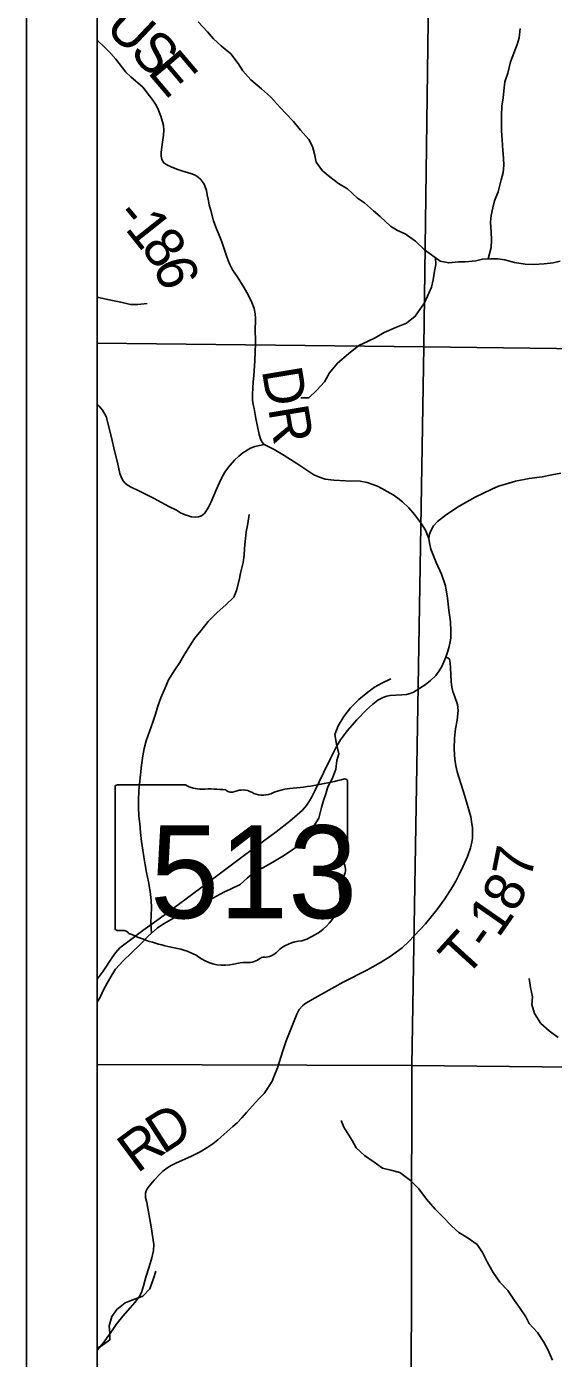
# Model space of a CAD drawing. Extents: x 0 to 34, y 0 to 22.
# Drawn here: x 23.417 to 24.164, y 15.161 to 17.051 of the extents above; entities that cross this region are included whole.
import ezdxf

# ---------------------------------------------------------------- set-up
doc = ezdxf.new("R2010")
doc.units = 0
for name, color, linetype in [('GM_X_Corporation', 7, 'Continuous'), ('GM_X_Minor_River', 7, 'Continuous'), ('GM_X_State_Route', 7, 'Continuous'), ('GM_X_State_Shield', 7, 'Continuous'), ('GM_X_Township_Road', 7, 'Continuous'), ('GM_X_Township_Road_Text', 7, 'Continuous'), ('SH_Data', 7, 'Continuous')]:
    doc.layers.add(name, color=color, linetype=linetype)

msp = doc.modelspace()

# ---------------------------------------------------------------- linework, layer by layer
at = {"layer": 'GM_X_Corporation'}
msp.add_lwpolyline([(23.5167, 20.3276), (23.5167, 14.5642), (23.7464, 14.562), (24.4108, 14.5557), (24.414, 14.5556), (24.9788, 14.5503), (25.0494, 14.5496), (25.56, 14.5392), (26.009, 14.53), (26.3333, 14.5233), (26.7998, 14.5186), (27.0057, 14.5136), (27.0124, 14.988), (27.0234, 16.6611), (27.0349, 17.5522)], dxfattribs=at)
msp.add_lwpolyline([(23.5167, 20.3276), (23.5167, 14.5642), (23.7464, 14.562), (24.4108, 14.5557), (24.414, 14.5556), (24.9788, 14.5503), (25.0494, 14.5496), (25.56, 14.5392), (26.009, 14.53), (26.3333, 14.5233), (26.7998, 14.5186), (27.0057, 14.5136), (27.0124, 14.988), (27.0234, 16.6611), (27.0349, 17.5522)], dxfattribs=at)
for points in [[(23.5167, 17.6305), (23.5167, 16.6012), (23.9803, 16.5962), (23.994, 17.626)], [(25.0136, 17.617), (24.9957, 16.5834), (23.9803, 16.5962), (23.994, 17.626)], [(23.5167, 16.6012), (23.5167, 15.5777), (23.9634, 15.5762), (23.9803, 16.5962)], [(23.9803, 16.5962), (24.9957, 16.5834), (24.9795, 15.5656), (23.9634, 15.5762)], [(23.5167, 15.5777), (23.5167, 14.5671), (23.9615, 14.5614), (23.9614, 14.5662), (23.9634, 15.5762)], [(23.9634, 15.5762), (24.9795, 15.5656), (24.9754, 14.552), (23.9615, 14.5614), (23.9614, 14.5662)]]:
    msp.add_lwpolyline(points, close=True, dxfattribs=at)
at = {"layer": 'GM_X_Minor_River'}
for points in [[(23.6601, 17.0576), (23.6734, 17.0433), (23.6818, 17.0334), (23.6928, 17.0232), (23.7065, 17.0119), (23.7168, 16.9982), (23.7236, 16.988), (23.7347, 16.9751), (23.7499, 16.9623), (23.7628, 16.9509), (23.7715, 16.9411), (23.7837, 16.9282), (23.7955, 16.9161), (23.8054, 16.9036), (23.8172, 16.8904), (23.8225, 16.8805), (23.8252, 16.8703), (23.8275, 16.8585), (23.8363, 16.846), (23.8469, 16.8377), (23.8594, 16.8282), (23.872, 16.8203), (23.8861, 16.8071), (23.8959, 16.8007), (23.9089, 16.7893), (23.9184, 16.7814), (23.9332, 16.7674), (23.9427, 16.7613), (23.9537, 16.7568), (23.9685, 16.7462), (23.9811, 16.7337), (23.9913, 16.7266), (24.0035, 16.7179), (24.0157, 16.7153), (24.0293, 16.7168), (24.0388, 16.7168), (24.054, 16.7184), (24.0635, 16.7207), (24.0752, 16.7211), (24.0855, 16.7212), (24.095, 16.7197), (24.109, 16.7159), (24.1242, 16.7133), (24.1363, 16.713), (24.1508, 16.7138), (24.1637, 16.7154), (24.1735, 16.7177)], [(24.0716, 16.721), (24.0759, 16.7371), (24.0763, 16.7481), (24.0759, 16.7591), (24.0751, 16.7731), (24.0758, 16.7826), (24.0781, 16.7933), (24.0807, 16.8032), (24.0856, 16.8161), (24.0902, 16.8332), (24.0928, 16.8438), (24.0939, 16.8541), (24.0931, 16.8639), (24.0923, 16.8749), (24.0912, 16.8901), (24.0904, 16.9026), (24.0903, 16.9247), (24.0911, 16.9376), (24.0929, 16.9497), (24.094, 16.9596), (24.0952, 16.9725), (24.0993, 16.9847), (24.1031, 17.0006), (24.1129, 17.0253), (24.1155, 17.0348), (24.117, 17.0481)], [(23.9968, 16.7226), (23.9971, 16.7129), (23.9956, 16.7034), (23.9933, 16.6913), (23.9911, 16.681), (23.9854, 16.6681), (23.9813, 16.6586), (23.9748, 16.6491), (23.968, 16.6396), (23.9559, 16.63), (23.9415, 16.6239), (23.924, 16.6166), (23.9112, 16.609), (23.9013, 16.604), (23.888, 16.5979), (23.8736, 16.5861), (23.8577, 16.5731), (23.8464, 16.5594), (23.8392, 16.5465), (23.8286, 16.5347), (23.8172, 16.524), (23.8059, 16.524)], [(23.5167, 16.6666), (23.5228, 16.6654), (23.5384, 16.6621), (23.5502, 16.6594), (23.5642, 16.6564), (23.5745, 16.6561), (23.5877, 16.6577)], [(23.594, 15.7642), (23.5931, 15.7789), (23.5935, 15.7892), (23.5938, 15.8002), (23.5934, 15.8104), (23.5919, 15.8233), (23.5896, 15.837), (23.5869, 15.8503), (23.585, 15.8609), (23.583, 15.8723), (23.5815, 15.8818), (23.5796, 15.8939), (23.578, 15.9068), (23.5772, 15.9197), (23.5761, 15.9299), (23.5753, 15.9429), (23.5753, 15.9527), (23.576, 15.966), (23.5767, 15.9755), (23.5782, 15.9888), (23.5797, 16.0025), (23.5816, 16.0158), (23.5835, 16.026), (23.5865, 16.037), (23.591, 16.0503), (23.5959, 16.0636), (23.5997, 16.075), (23.6027, 16.0861), (23.6072, 16.0982), (23.6132, 16.1123), (23.6178, 16.1237), (23.6268, 16.1378), (23.634, 16.148), (23.6397, 16.1579), (23.648, 16.172), (23.6548, 16.1823), (23.6639, 16.1933), (23.6741, 16.2062), (23.687, 16.2192), (23.6995, 16.2302), (23.7109, 16.2409), (23.7146, 16.2504), (23.718, 16.2648), (23.7203, 16.2751), (23.7237, 16.2899), (23.7251, 16.3005), (23.7259, 16.3104), (23.727, 16.3241), (23.7281, 16.3336), (23.7304, 16.3454), (23.7322, 16.3583)], [(23.8439, 15.9715), (23.8507, 15.984), (23.8552, 15.9969), (23.8567, 16.0091), (23.8597, 16.0186), (23.8563, 16.0322), (23.854, 16.0459), (23.8589, 16.0581), (23.8668, 16.0714), (23.8763, 16.0839), (23.888, 16.0957), (23.9009, 16.106), (23.9104, 16.1133), (23.9206, 16.1186), (23.9335, 16.1251)], [(23.5167, 15.6662), (23.5212, 15.6732), (23.5258, 15.6834), (23.5307, 15.6929), (23.5367, 15.7032), (23.5428, 15.7127), (23.5534, 15.7249), (23.5655, 15.7363), (23.5776, 15.7481), (23.589, 15.7599), (23.6022, 15.7714), (23.6117, 15.7775), (23.625, 15.7855), (23.6344, 15.7901), (23.6466, 15.7958), (23.6568, 15.8015), (23.6708, 15.8099), (23.6807, 15.8138), (23.6966, 15.8222), (23.7061, 15.8264), (23.7197, 15.8333), (23.7296, 15.842), (23.7421, 15.8527), (23.7527, 15.8573), (23.7682, 15.8664), (23.7804, 15.8733), (23.794, 15.8821), (23.8046, 15.8901), (23.8156, 15.9015), (23.8231, 15.9144), (23.8311, 15.927), (23.8352, 15.9422), (23.8379, 15.9521), (23.8413, 15.9616), (23.8439, 15.9715)], [(24.171, 15.6157), (24.1581, 15.6255), (24.1463, 15.6358), (24.1372, 15.6498), (24.1333, 15.6627), (24.1345, 15.6737), (24.1318, 15.6869), (24.1298, 15.6998)], [(24.1629, 15.1579), (24.1564, 15.1731), (24.1507, 15.1837), (24.1416, 15.1973), (24.1298, 15.2098), (24.1252, 15.2197), (24.1161, 15.2325), (24.1088, 15.2428), (24.0997, 15.2568), (24.0879, 15.2689), (24.0788, 15.2825), (24.07, 15.2977), (24.0635, 15.3106), (24.0559, 15.3219), (24.043, 15.331), (24.0301, 15.3393), (24.0198, 15.348), (24.0061, 15.3624), (23.9962, 15.3722), (23.9841, 15.3866), (23.973, 15.401), (23.9612, 15.4131), (23.946, 15.4241), (23.9335, 15.4278), (23.9217, 15.4304), (23.9099, 15.4391), (23.8959, 15.4486), (23.8841, 15.4591), (23.8788, 15.4698), (23.8666, 15.4887), (23.8628, 15.4982)], [(23.5167, 15.1757), (23.5223, 15.1778), (23.5345, 15.1866), (23.5348, 15.1961), (23.534, 15.2067), (23.5374, 15.22), (23.5446, 15.2299), (23.5563, 15.2394), (23.5658, 15.2432), (23.5814, 15.249), (23.5916, 15.2593), (23.5965, 15.2737), (23.5999, 15.2844)]]:
    msp.add_lwpolyline(points, dxfattribs=at)
at = {"layer": 'GM_X_State_Route'}
msp.add_lwpolyline([(23.5167, 15.6987), (23.5254, 15.7102), (23.538, 15.7296), (23.5429, 15.7361), (23.5491, 15.7433), (23.5641, 15.7546), (23.5816, 15.7676), (23.6045, 15.7844), (23.6285, 15.8019), (23.6689, 15.8322), (23.7256, 15.8745), (23.7708, 15.908), (23.79, 15.9229), (23.8005, 15.9319), (23.808, 15.9387), (23.8137, 15.9453), (23.8181, 15.9518), (23.8213, 15.9573), (23.8258, 15.9659), (23.8382, 15.9926), (23.8477, 16.012), (23.8564, 16.029), (23.8622, 16.0383), (23.8661, 16.0442), (23.8714, 16.051), (23.8851, 16.0668), (23.899, 16.0809), (23.9079, 16.0892), (23.915, 16.0945), (23.9234, 16.0991), (23.928, 16.1006), (23.9323, 16.1014), (23.9404, 16.102), (23.9491, 16.1021), (23.9556, 16.1029), (23.9609, 16.1044), (23.9654, 16.1062), (23.9747, 16.1115), (23.9821, 16.1165), (23.9897, 16.1225), (23.9971, 16.1298), (23.9997, 16.1331), (24.002, 16.1364), (24.0056, 16.1426), (24.0114, 16.1556), (24.0145, 16.1641), (24.0163, 16.1708), (24.0185, 16.1828), (24.0186, 16.1931), (24.0179, 16.2057), (24.0159, 16.2226), (24.014, 16.2394), (24.0111, 16.2572), (24.0054, 16.2735), (23.998, 16.2899), (23.9932, 16.3019), (23.9904, 16.309), (23.9881, 16.3182), (23.9875, 16.3241), (23.9885, 16.3303), (23.99, 16.3351), (23.9941, 16.3421), (23.9997, 16.3484), (24.0125, 16.3584), (24.0302, 16.3702), (24.0529, 16.383), (24.0767, 16.3941), (24.0863, 16.3982), (24.0963, 16.4014), (24.1103, 16.4054), (24.1299, 16.4091), (24.1484, 16.4118), (24.1617, 16.4145), (24.1746, 16.4171)], dxfattribs=at)
at = {"layer": 'GM_X_State_Shield'}
for p, q in [((23.642, 15.9746), (23.5455, 15.9746)), ((23.8718, 15.8749), (23.8718, 15.9796)), ((23.5422, 15.9712), (23.5422, 15.7711)), ((23.8718, 15.8749), (23.8718, 15.8749))]:
    msp.add_line(p, q, dxfattribs=at)
for centre, major_axis, start_param, end_param in [((23.546, 15.9716), (0.00382, 0), 1.712693, 3.28349), ((23.665, 15.9979), (0.037, 0), 4.042523, 4.731795), ((23.7544, 16.2475), (0.3495, 0), 4.814394, 5.042369), ((23.8682, 15.98), (0.00367, 0), 6.141152, 7.989035), ((23.6773, 15.8623), (0.133, 0), 1.404758, 1.657858), ((23.7075, 15.9726), (0.0107, 0), 3.836095, 5.185415), ((23.7231, 15.9495), (0.0222, 0), 0.950623, 2.079405), ((23.7518, 15.9812), (0.0267, 0), 4.081561, 5.145723), ((23.799, 15.9135), (0.0703, 0), 1.699011, 2.107814), ((23.871, 15.8672), (0.00568, 0), 1.883978, 3.671073), ((23.8349, 15.854), (0.0341, 0), 5.934695, 6.695948), ((23.8679, 15.8745), (0.00393, 0), 5.05454, 6.418171), ((23.885, 15.8311), (0.0248, 0), 2.387724, 3.262537), ((23.774, 15.8178), (0.0874, 0), 5.101752, 6.440018), ((23.5461, 15.7706), (0.00385, 0), 3.00124, 4.508301), ((23.5466, 15.7911), (0.0294, 0), 4.665946, 4.897461), ((23.5527, 15.7595), (0.0106, 0), 0.519207, 1.627899), ((23.6865, 15.9393), (0.2524, 0), 4.195997, 4.488961), ((23.8109, 15.7149), (0.0479, 0), 1.647645, 2.488434), ((23.6112, 15.6812), (0.079, 0), 0.823519, 1.323587), ((23.6966, 15.7585), (0.0501, 0), 4.026481, 4.996735), ((23.7293, 15.7435), (0.0267, 0), 4.691044, 5.507374), ((23.7534, 15.7242), (0.00752, 0), 1.147584, 2.315152), ((23.7502, 15.7517), (0.0282, 0), 4.937069, 5.64225), ((23.7256, 15.6893), (0.0412, 0), 1.495662, 1.94098)]:
    msp.add_ellipse(centre, major_axis=major_axis, ratio=0.8, start_param=start_param, end_param=end_param, dxfattribs=at)
at = {"layer": 'GM_X_Township_Road'}
for points in [[(23.7535, 16.4577), (23.7506, 16.4613), (23.7485, 16.4656), (23.7464, 16.4719), (23.7418, 16.4945), (23.7393, 16.5089), (23.7382, 16.5143), (23.7373, 16.5206), (23.737, 16.5289), (23.7376, 16.5375), (23.7382, 16.5467), (23.739, 16.5552), (23.7403, 16.5761), (23.7412, 16.6012), (23.741, 16.6235), (23.7413, 16.6307), (23.7413, 16.6365), (23.7409, 16.6428), (23.7396, 16.6505), (23.7362, 16.6593), (23.7308, 16.67), (23.7252, 16.6797), (23.7152, 16.6958), (23.7086, 16.7057), (23.7049, 16.7132), (23.7028, 16.7185), (23.6996, 16.727), (23.696, 16.738), (23.6935, 16.7451), (23.69, 16.7545), (23.6852, 16.7661), (23.682, 16.7749), (23.6779, 16.7896), (23.6759, 16.7975), (23.6742, 16.8057), (23.6727, 16.8119), (23.6717, 16.8179), (23.67, 16.8233), (23.6685, 16.8273), (23.6664, 16.8306), (23.6636, 16.8341), (23.6599, 16.8372), (23.656, 16.8398), (23.6497, 16.8422), (23.6382, 16.8457), (23.6297, 16.8485), (23.6216, 16.8517), (23.6154, 16.8544), (23.6113, 16.8573), (23.6084, 16.862), (23.6077, 16.8667), (23.6076, 16.8725), (23.6093, 16.8869), (23.6109, 16.8964), (23.6113, 16.9036), (23.6109, 16.9103), (23.6096, 16.9157), (23.6071, 16.9236), (23.6037, 16.9323), (23.6003, 16.9391), (23.5955, 16.9463), (23.5815, 16.9649), (23.5645, 16.9795), (23.5576, 16.9859), (23.543, 17.0045), (23.5359, 17.0125), (23.5267, 17.0221), (23.5177, 17.0305), (23.5167, 17.0312)], [(23.5167, 16.5148), (23.5191, 16.5124), (23.5241, 16.5065), (23.5295, 16.4974), (23.5365, 16.4696), (23.5419, 16.4468), (23.5454, 16.4319), (23.5491, 16.4164), (23.5518, 16.4095), (23.5538, 16.4059), (23.5564, 16.4027), (23.5593, 16.4004), (23.5642, 16.3974), (23.5778, 16.3908), (23.5975, 16.3811), (23.6186, 16.3697), (23.6291, 16.3642), (23.6351, 16.3607), (23.6418, 16.3578), (23.6463, 16.3562), (23.6503, 16.3551), (23.6558, 16.3543), (23.6605, 16.355), (23.6646, 16.3564), (23.6696, 16.3603), (23.6748, 16.3685), (23.6787, 16.3763), (23.6861, 16.3942), (23.6904, 16.4037), (23.6932, 16.4097), (23.6981, 16.4181), (23.7017, 16.4237), (23.7053, 16.4283), (23.7114, 16.4354), (23.7177, 16.4412), (23.7234, 16.4457), (23.7298, 16.4497), (23.7345, 16.4523), (23.7403, 16.4546), (23.7535, 16.4577)], [(23.7535, 16.4577), (23.7678, 16.4506), (23.7782, 16.4443), (23.8001, 16.4306), (23.8128, 16.4219), (23.8243, 16.4147), (23.8322, 16.4111), (23.8401, 16.4084), (23.8526, 16.4068), (23.869, 16.4062), (23.8898, 16.4053), (23.8998, 16.4035), (23.908, 16.401), (23.9144, 16.3986), (23.9208, 16.3949), (23.9283, 16.3907), (23.9366, 16.3859), (23.9435, 16.3816), (23.9501, 16.3762), (23.959, 16.3675), (23.9668, 16.3583), (23.9769, 16.3452), (23.9826, 16.3358), (23.9875, 16.3241)], [(24.0114, 16.1556), (24.0143, 16.1548), (24.0166, 16.153), (24.0177, 16.1471), (24.0181, 16.1408), (24.019, 16.1211), (24.0201, 16.1133), (24.0213, 16.1071), (24.0243, 16.0994), (24.0281, 16.0884), (24.029, 16.0802), (24.0275, 16.0663), (24.0254, 16.0542), (24.0237, 16.041), (24.0231, 16.0262), (24.0237, 16.0171), (24.0243, 16.0108), (24.0259, 16.0017), (24.0277, 15.9931), (24.0298, 15.9852), (24.0364, 15.9647), (24.0407, 15.9505), (24.0439, 15.9392), (24.0471, 15.929), (24.0481, 15.9224), (24.0493, 15.9137), (24.0494, 15.9056), (24.0492, 15.8986), (24.048, 15.891), (24.0465, 15.8849), (24.0421, 15.8726), (24.0359, 15.8589), (24.0306, 15.8471), (24.0256, 15.8379), (24.0209, 15.83), (24.0099, 15.8126), (23.9987, 15.797), (23.9825, 15.7771), (23.9588, 15.7521), (23.9495, 15.7431), (23.9324, 15.7308), (23.9188, 15.7226), (23.9004, 15.7122), (23.8659, 15.6946), (23.822, 15.6698), (23.8114, 15.6639), (23.808, 15.6611), (23.8033, 15.6558), (23.7999, 15.6489), (23.7848, 15.6112), (23.7824, 15.6041), (23.7801, 15.5971), (23.7725, 15.5729), (23.7675, 15.5601), (23.7649, 15.5538), (23.7617, 15.5487), (23.7575, 15.542), (23.7535, 15.5366), (23.7455, 15.5284), (23.7285, 15.5094), (23.722, 15.5017), (23.7154, 15.4949), (23.7092, 15.4894), (23.6882, 15.4705), (23.6809, 15.4651), (23.6738, 15.4601), (23.6628, 15.4538), (23.6507, 15.4475), (23.6286, 15.4377), (23.6219, 15.4344), (23.6155, 15.4306), (23.61, 15.4262), (23.6056, 15.422), (23.5975, 15.4134), (23.5904, 15.4047), (23.5879, 15.4012), (23.5861, 15.3982), (23.5853, 15.3952), (23.5852, 15.3922), (23.5855, 15.3889), (23.5873, 15.3818), (23.5933, 15.3472), (23.5971, 15.3223), (23.5969, 15.3134), (23.5945, 15.3032), (23.5905, 15.2905), (23.586, 15.276), (23.5825, 15.2633), (23.5797, 15.2541), (23.5765, 15.2477), (23.57, 15.2396), (23.5634, 15.2324), (23.5533, 15.2206), (23.5436, 15.2088), (23.536, 15.1973), (23.5311, 15.1901), (23.5268, 15.1842), (23.5167, 15.1722)]]:
    msp.add_lwpolyline(points, dxfattribs=at)
at = {"layer": 'SH_Data'}
for points in [[(23.4167, 21), (30.4167, 21), (30.4167, 14), (23.4167, 14)], [(23.5167, 20.9), (30.3167, 20.9), (30.3167, 14.1), (23.5167, 14.1)]]:
    msp.add_lwpolyline(points, close=True, dxfattribs=at)

# ---------------------------------------------------------------- texts
at = {"layer": 'GM_X_State_Shield'}
msp.add_text('513', height=0.13184, dxfattribs=at).set_placement((23.5917, 15.7852))
at = {"layer": 'GM_X_Township_Road_Text'}
for s, height, rotation, p in [('U', 0.0568, 316.7209, (23.5258, 17.0471)), ('S', 0.0568, 312.6576, (23.5614, 17.0135)), ('E', 0.0568, 310.334, (23.587, 16.9858)), ('-', 0.0568, 309.7486, (23.5405, 16.7813)), ('1', 0.0568, 308.5281, (23.5552, 16.7636)), ('8', 0.0568, 308.5786, (23.5771, 16.7362)), ('6', 0.0568, 287.78, (23.5963, 16.7136)), ('DR', 0.05682, 279.4626, (23.7502, 16.563)), ('7', 0.0568, 78.6999, (24.1321, 15.839)), ('8', 0.0568, 62.6028, (24.1103, 15.7916)), ('1', 0.0568, 55.2072, (24.0862, 15.756)), ('T', 0.0568, 47.7799, (24.039, 15.6993)), ('-', 0.0568, 54.3877, (24.0721, 15.7363)), ('D', 0.0568, 32.8302, (23.6101, 15.4493)), ('R', 0.0568, 36.5381, (23.5734, 15.4221))]:
    msp.add_text(s, height=height, rotation=rotation, dxfattribs=at).set_placement(p)

doc.saveas('drawing.dxf')
